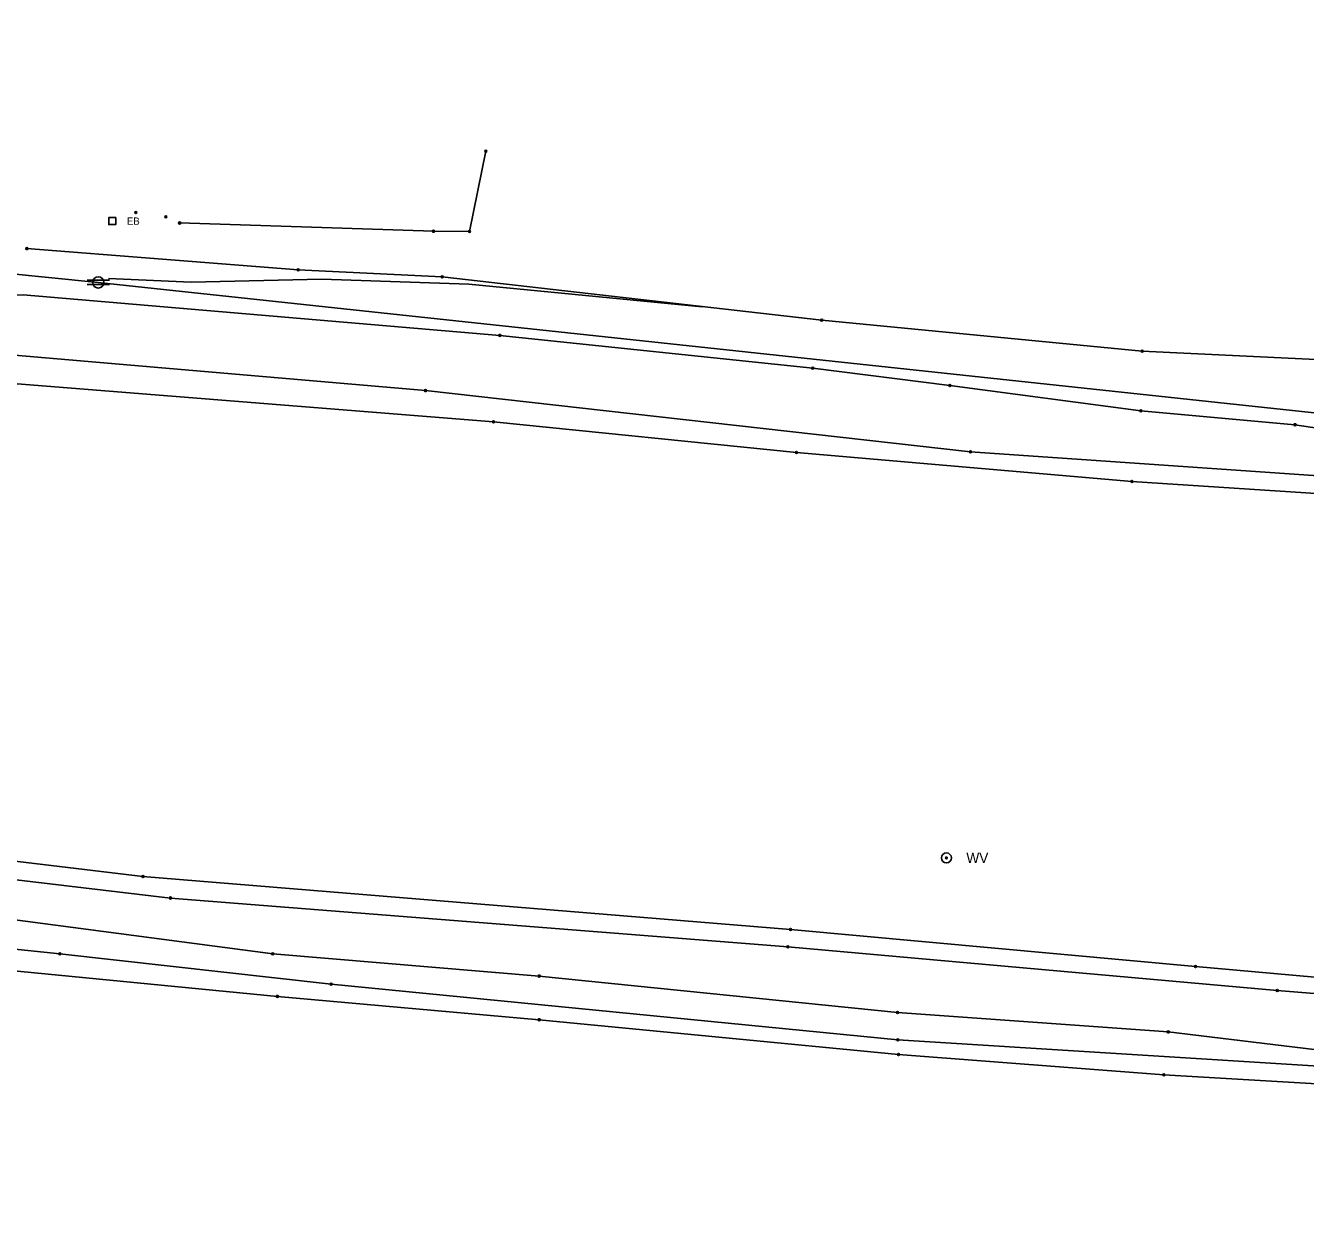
# Model space of a CAD drawing. Extents: x 20500343 to 20505311, y 7953484 to 7954193.
# Drawn here: x 20501927.3 to 20502176.1, y 7953761.4 to 7953994.1 of the extents above; entities that cross this region are included whole.
import ezdxf

# ---------------------------------------------------------------- set-up
doc = ezdxf.new("R2010")
doc.units = 0
for name, color, linetype in [('C-PROP-LINE-LOT', 7, 'Continuous'), ('V-ANNO-BNDY', 7, 'Continuous'), ('V-ANNO-NOTE', 7, 'Continuous'), ('V-CTRL-HVPT', 7, 'Continuous'), ('V-SITE-FENC', 7, 'Continuous'), ('V-SSWR-STRC', 7, 'Continuous')]:
    doc.layers.add(name, color=color, linetype=linetype)

msp = doc.modelspace()

# ---------------------------------------------------------------- linework, layer by layer
at = {"layer": 'C-PROP-LINE-LOT'}
for points in [[(20501461.7, 7953994.07), (20501696.91, 7953968.73), (20501941.48, 7953944.15)], [(20501957.29, 7953955.69), (20502006.64, 7953954.08), (20502013.65, 7953954.05), (20502016.83, 7953969.65)], [(20501786.53, 7953958.21), (20501802.89, 7953943.86), (20501839.77, 7953931.6), (20501880.96, 7953927.96), (20502018.29, 7953917.03), (20502077.19, 7953911.09), (20502142.41, 7953905.45), (20502199.08, 7953901.71), (20502241.51, 7953895.28), (20502292.25, 7953890.73), (20502324.65, 7953886.92), (20502369.24, 7953880.93), (20502409.05, 7953877.23), (20502443.31, 7953873.2), (20502481.36, 7953863.28), (20502512.4, 7953858.05), (20502594.55, 7953857.22)], [(20501786.53, 7953958.21), (20501798.37, 7953955.39), (20501845.31, 7953947.9), (20501861.48, 7953946.79), (20501912.59, 7953941.56), (20501926.87, 7953941.71), (20502019.52, 7953933.84), (20502080.36, 7953927.46), (20502107.02, 7953924.08), (20502144.15, 7953919.15), (20502174.11, 7953916.47), (20502211.46, 7953910.85), (20502243.75, 7953903.07), (20502293.11, 7953894.8), (20502325.39, 7953891.51), (20502370.1, 7953885.96), (20502409.42, 7953880.13), (20502443.48, 7953874.15), (20502481.41, 7953864.06), (20502512.42, 7953858.66), (20502594.72, 7953856.58)], [(20501927.57, 7953950.71), (20501980.32, 7953946.58), (20502008.33, 7953945.23), (20502082.1, 7953936.78), (20502144.41, 7953930.79), (20502205.22, 7953927.86), (20502265.66, 7953921.64), (20502325.14, 7953913.11), (20502432.98, 7953900.65), (20502447.13, 7953900.6), (20502499.42, 7953893.79), (20502538.42, 7953891.09), (20502589.85, 7953886.97), (20502611.07, 7953885.99)], [(20501943.45, 7953944.87), (20501959.51, 7953944.18), (20501984.91, 7953944.79), (20502013.5, 7953943.79), (20502058.85, 7953939.41)], [(20501941.48, 7953944.15), (20502193.58, 7953917.07), (20502451.16, 7953888.46), (20502584.33, 7953884.2), (20502691.76, 7953878.47)], [(20501804.54, 7953940.37), (20502005.09, 7953923.1), (20502111.03, 7953911.19), (20502201.18, 7953904.98), (20502309.45, 7953894.18), (20502395.03, 7953885.06)], [(20501822.69, 7953839.61), (20501870.85, 7953834.49), (20501955.49, 7953824.45), (20502075.53, 7953814.96), (20502170.68, 7953806.48), (20502238.89, 7953800.97), (20502334.58, 7953792.75), (20502432.59, 7953781.98), (20502508.31, 7953776.06), (20502531.87, 7953776.49), (20502581.28, 7953773.17)], [(20501871.18, 7953838.12), (20501950.16, 7953828.62), (20502076.03, 7953818.34), (20502154.77, 7953811.13), (20502239.61, 7953803.57), (20502335.63, 7953794.91), (20502433.27, 7953786.61), (20502509.73, 7953784.12), (20502531.75, 7953782.62), (20502583.58, 7953780.86)], [(20501766.01, 7953834.76), (20501821.75, 7953833.43), (20501869.61, 7953826.07), (20501921.27, 7953820.74), (20501975.38, 7953813.59), (20502027.18, 7953809.28), (20502096.84, 7953802.19), (20502149.48, 7953798.41), (20502206.76, 7953791.49), (20502246.02, 7953783), (20502332.45, 7953784.05), (20502423.49, 7953775.99), (20502457.77, 7953772.43), (20502468.01, 7953774.31), (20502490.69, 7953772.12), (20502532.01, 7953768.89), (20502567.5, 7953767.25)], [(20501765.8, 7953831.13), (20501934, 7953813.62), (20501986.76, 7953807.7), (20502096.89, 7953796.9), (20502224.25, 7953788.94), (20502278.96, 7953784.08), (20502408.88, 7953781.44), (20502417.83, 7953784.37), (20502465.46, 7953783.06), (20502531.65, 7953780.57), (20502583.55, 7953776.2)], [(20501923.78, 7953810.45), (20501976.29, 7953805.33), (20502027.19, 7953800.79), (20502097.04, 7953794.03), (20502148.61, 7953790.06), (20502191.57, 7953787.56), (20502246.17, 7953780.88), (20502423.34, 7953773.23), (20502457.56, 7953769.95), (20502471.39, 7953769.52), (20502491.18, 7953768.99), (20502531.55, 7953766.92), (20502567.17, 7953761.38)]]:
    msp.add_lwpolyline(points, dxfattribs=at)
at = {"layer": 'V-ANNO-BNDY'}
for p, q in [((20501948.75, 7953957.72), (20501948.75, 7953957.72)), ((20501954.62, 7953956.89), (20501954.62, 7953956.89))]:
    msp.add_line(p, q, dxfattribs=at)
at = {"layer": 'V-ANNO-NOTE'}
for centre in [(20502016.83, 7953969.65), (20501948.75, 7953957.72), (20501954.62, 7953956.89), (20501957.29, 7953955.69), (20502006.64, 7953954.08), (20502013.65, 7953954.05), (20501927.57, 7953950.71), (20501980.32, 7953946.58), (20502008.33, 7953945.23), (20502082.1, 7953936.78), (20502019.52, 7953933.84), (20502144.41, 7953930.79), (20502080.36, 7953927.46), (20502005.09, 7953923.1), (20502107.02, 7953924.08), (20502144.15, 7953919.15), (20502018.29, 7953917.03), (20502174.11, 7953916.47), (20502077.19, 7953911.09), (20502111.03, 7953911.19), (20502142.41, 7953905.45), (20501950.16, 7953828.62), (20501955.49, 7953824.45), (20502076.03, 7953818.34), (20501934, 7953813.62), (20501975.38, 7953813.59), (20502075.53, 7953814.96), (20502154.77, 7953811.13), (20501986.76, 7953807.7), (20502027.18, 7953809.28), (20501976.29, 7953805.33), (20502170.68, 7953806.48), (20502027.19, 7953800.79), (20502096.84, 7953802.19), (20502149.48, 7953798.41), (20502096.89, 7953796.9), (20502097.04, 7953794.03), (20502148.61, 7953790.06)]:
    msp.add_circle(centre, 0.2, dxfattribs=at)
at = {"layer": 'V-CTRL-HVPT'}
for p, q in [((20501939.28, 7953944.59), (20501943.68, 7953944.59)), ((20501939.28, 7953943.71), (20501943.68, 7953943.71))]:
    msp.add_line(p, q, dxfattribs=at)
msp.add_circle((20501941.48, 7953944.15), 1.1, dxfattribs=at)
at = {"layer": 'V-SITE-FENC'}
msp.add_lwpolyline([(20501944.19, 7953955.37), (20501944.19, 7953955.37), (20501944.88, 7953955.37), (20501944.88, 7953956.74), (20501943.5, 7953956.74), (20501943.5, 7953955.37), (20501944.19, 7953955.37)], dxfattribs=at)
at = {"layer": 'V-SSWR-STRC'}
for radius in [0.971, 0.162]:
    msp.add_circle((20502106.35, 7953832.25), radius, dxfattribs=at)

# ---------------------------------------------------------------- texts
at = {"layer": 'V-SITE-FENC'}
msp.add_text('EB', height=1.399, dxfattribs=at).set_placement((20501947.03, 7953955.36))
at = {"layer": 'V-SSWR-STRC'}
msp.add_text('WV', height=1.982, dxfattribs=at).set_placement((20502110.23, 7953831.26))

doc.saveas('drawing.dxf')
